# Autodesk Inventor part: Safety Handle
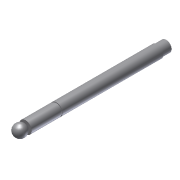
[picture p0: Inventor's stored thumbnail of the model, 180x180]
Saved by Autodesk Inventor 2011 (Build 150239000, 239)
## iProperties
Shininess: 77.0
Length Units: 11269
Angle Units: 11279
Time Units: 11290
Mass Units: 11283
Length Display Precision: 3
Angle Display Precision: 2
Created: 2002-02
Part Number: Safety Handle
Document SubType Name: Modeling
Designer: ***
Density: 1 g/cm^3
Density: 0.0
Volumn: 0.0
Area: 0.0
PropertySet Name: Model Information
Control State: 0
Master: False
Checked Out: False
Author: ***
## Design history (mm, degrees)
sketch "Sketch1"
  geometry: L1 (0, 205)-(8, 205); L2 (8, 205)-(8, 192); L3 (8, 192)-(9, 192); L4 (9, 192)-(9, 45); L5 (9, 45)-(8, 45); L6 (8, 45)-(8, 43); L7 (8, 43)-(9, 43); L8 (9, 43)-(9, 0); L9 (9, 0)-(0, 0); L10 (0, 0)-(0, 205)
  constraints: 20 end point, 7 parallel, 1 collinear, 1 horizontal, 1 perpendicular
  dimensions: "d0" = 13 distance of L1.end L2.end; "d1" = 2 distance of L4.end L7.end; "d2" = 43 distance of L7.end L8.end; "d3" = 205 distance of L9.end L1.start; "d4" = 16 diameter of L2 L10; "d5" = 18 diameter of L4 L10; "d6" = 16 diameter of L6.end L10
revolve "Revolution1" sketch "Sketch1" stored, may be unused: angle "d7" = 90 deg
sketch "Sketch2"
  geometry: L1 (0, 1)-(0, -17); L2 (-9, 0)-(9, 0) reference; A1 r 9 centre (0, -8) between (0, -17) and (0, 1)
  constraints: 2 end point, 2 point on circle, 1 centre point, 1 midpoint, 1 vertical
  dimensions: "d8" = 9 radius of A1; "d9" = 1 distance from line of L2 L1.start
revolve "Revolution2" sketch "Sketch2" stored, may be unused: angle "d10" = 90 deg
body "Solid1"
